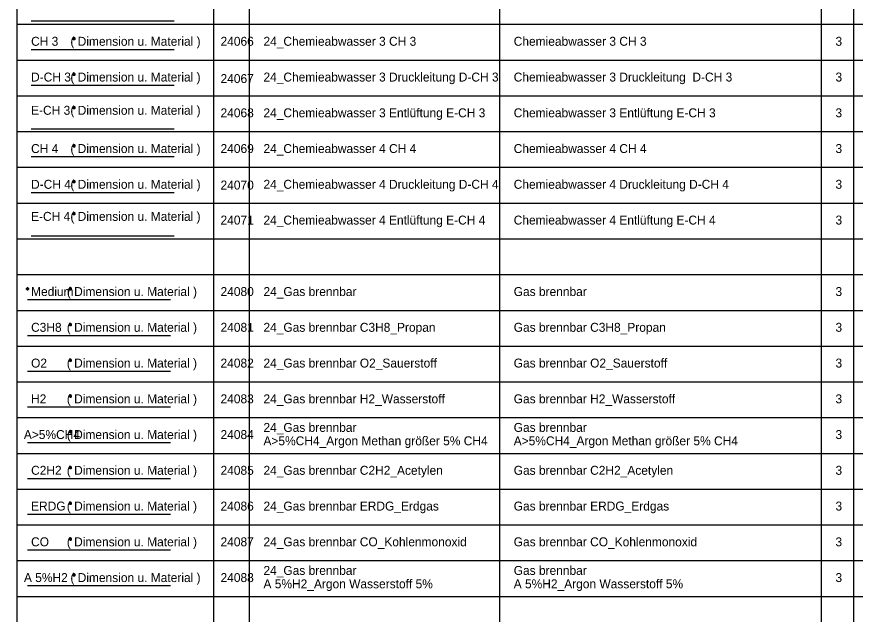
# Model space of a CAD drawing. Extents: x -29 to 48, y -113 to 16.
# Drawn here: x 0 to 23.45, y -47.5 to -30.79 of the extents above; entities that cross this region are included whole.
import ezdxf

# ---------------------------------------------------------------- set-up
doc = ezdxf.new("R2010")
doc.units = 0
for name, color, linetype in [('24_Chemieabwasser 2 Entlüftung E-CH2', 7, 'Continuous'), ('24_Chemieabwasser 3 CH 3', 7, 'Continuous'), ('24_Chemieabwasser 3 Druckleitung D-CH 3', 7, 'Continuous'), ('24_Chemieabwasser 3 Entlüftung E-CH 3', 7, 'Continuous'), ('24_Chemieabwasser 4 CH 4', 7, 'Continuous'), ('24_Chemieabwasser 4 Druckleitung CH 4', 7, 'Continuous'), ('24_Chemieabwasser 4 Entlüftung E-CH 4', 7, 'Continuous'), ('24_Gas brennbar', 7, 'Continuous'), ('24_Gas brennbar A 5%H2_Argon Wasserstoff 5%', 7, 'Continuous'), ('24_Gas brennbar A-5%CH4_Argon Methan größer 5% CH4', 7, 'Continuous'), ('24_Gas brennbar C2H2_Acetylen', 7, 'Continuous'), ('24_Gas brennbar C3H8_Propan', 7, 'Continuous'), ('24_Gas brennbar CO_Kohlenmonoxid', 7, 'Continuous'), ('24_Gas brennbar ERDG_Erdgas', 7, 'Continuous'), ('24_Gas brennbar H2_Wasserstoff', 7, 'Continuous'), ('24_Gas brennbar O2_Sauerstoff', 7, 'Continuous'), ('Default', 7, 'Continuous')]:
    doc.layers.add(name, color=color, linetype=linetype)

msp = doc.modelspace()

# ---------------------------------------------------------------- linework, layer by layer
at = {"layer": '24_Chemieabwasser 2 Entlüftung E-CH2'}
msp.add_line((0.4, -30.902), (4.4, -30.902), dxfattribs=at)
at = {"layer": '24_Chemieabwasser 3 CH 3'}
for p, q in [((1.556, -31.4), (1.644, -31.4)), ((1.569, -31.369), (1.631, -31.431)), ((1.631, -31.369), (1.569, -31.431)), ((1.6, -31.356), (1.6, -31.444)), ((0.4, -31.7), (4.4, -31.7)), ((1.6, -32.356), (1.6, -32.444)), ((1.556, -32.4), (1.644, -32.4)), ((1.569, -32.369), (1.631, -32.431)), ((1.631, -32.369), (1.569, -32.431))]:
    msp.add_line(p, q, dxfattribs=at)
at = {"layer": '24_Chemieabwasser 3 Druckleitung D-CH 3'}
msp.add_line((0.4, -32.7), (4.4, -32.7), dxfattribs=at)
at = {"layer": '24_Chemieabwasser 3 Entlüftung E-CH 3'}
for p, q in [((1.569, -33.299), (1.631, -33.361)), ((1.631, -33.299), (1.569, -33.361)), ((1.6, -33.286), (1.6, -33.374)), ((1.556, -33.33), (1.644, -33.33)), ((0.4, -33.922), (4.4, -33.922))]:
    msp.add_line(p, q, dxfattribs=at)
at = {"layer": '24_Chemieabwasser 4 CH 4'}
for p, q in [((1.556, -34.4), (1.644, -34.4)), ((1.569, -34.369), (1.631, -34.431)), ((1.631, -34.369), (1.569, -34.431)), ((1.6, -34.356), (1.6, -34.444)), ((0.4, -34.7), (4.4, -34.7)), ((1.556, -35.4), (1.644, -35.4))]:
    msp.add_line(p, q, dxfattribs=at)
at = {"layer": '24_Chemieabwasser 4 Druckleitung CH 4'}
for p, q in [((1.569, -35.369), (1.631, -35.431)), ((1.631, -35.369), (1.569, -35.431)), ((1.6, -35.356), (1.6, -35.444)), ((0.4, -35.7), (4.4, -35.7))]:
    msp.add_line(p, q, dxfattribs=at)
at = {"layer": '24_Chemieabwasser 4 Entlüftung E-CH 4'}
for p, q in [((1.556, -36.297), (1.644, -36.297)), ((1.569, -36.265), (1.631, -36.328)), ((1.631, -36.265), (1.569, -36.328)), ((1.6, -36.252), (1.6, -36.341)), ((0.4, -36.916), (4.4, -36.916))]:
    msp.add_line(p, q, dxfattribs=at)
at = {"layer": '24_Gas brennbar'}
for p, q in [((0.256, -38.4), (0.344, -38.4)), ((0.269, -38.369), (0.331, -38.431)), ((0.331, -38.369), (0.269, -38.431)), ((0.3, -38.356), (0.3, -38.444)), ((1.456, -38.4), (1.544, -38.4)), ((1.469, -38.369), (1.531, -38.431)), ((1.531, -38.369), (1.469, -38.431)), ((1.5, -38.356), (1.5, -38.444)), ((0.3, -38.7), (4.3, -38.7))]:
    msp.add_line(p, q, dxfattribs=at)
at = {"layer": '24_Gas brennbar A 5%H2_Argon Wasserstoff 5%'}
for p, q in [((1.556, -46.4), (1.644, -46.4)), ((1.569, -46.369), (1.631, -46.431)), ((1.631, -46.369), (1.569, -46.431)), ((1.6, -46.356), (1.6, -46.444)), ((0.3, -46.7), (4.3, -46.7))]:
    msp.add_line(p, q, dxfattribs=at)
at = {"layer": '24_Gas brennbar A-5%CH4_Argon Methan größer 5% CH4'}
for p, q in [((1.458, -42.4), (1.546, -42.4)), ((1.471, -42.369), (1.533, -42.431)), ((1.533, -42.369), (1.471, -42.431)), ((1.502, -42.356), (1.502, -42.444)), ((0.3, -42.7), (4.3, -42.7))]:
    msp.add_line(p, q, dxfattribs=at)
at = {"layer": '24_Gas brennbar C2H2_Acetylen'}
for p, q in [((1.469, -43.369), (1.531, -43.431)), ((1.531, -43.369), (1.469, -43.431)), ((1.5, -43.356), (1.5, -43.444)), ((1.456, -43.4), (1.544, -43.4)), ((0.3, -43.7), (4.3, -43.7))]:
    msp.add_line(p, q, dxfattribs=at)
at = {"layer": '24_Gas brennbar C3H8_Propan'}
for p, q in [((1.456, -39.4), (1.544, -39.4)), ((1.469, -39.369), (1.531, -39.431)), ((1.531, -39.369), (1.469, -39.431)), ((1.5, -39.356), (1.5, -39.444)), ((0.3, -39.7), (4.3, -39.7))]:
    msp.add_line(p, q, dxfattribs=at)
at = {"layer": '24_Gas brennbar CO_Kohlenmonoxid'}
for p, q in [((1.456, -45.4), (1.544, -45.4)), ((1.469, -45.369), (1.531, -45.431)), ((1.531, -45.369), (1.469, -45.431)), ((1.5, -45.356), (1.5, -45.444)), ((0.3, -45.7), (4.3, -45.7))]:
    msp.add_line(p, q, dxfattribs=at)
at = {"layer": '24_Gas brennbar ERDG_Erdgas'}
for p, q in [((1.456, -44.4), (1.544, -44.4)), ((1.469, -44.369), (1.531, -44.431)), ((1.531, -44.369), (1.469, -44.431)), ((1.5, -44.356), (1.5, -44.444)), ((0.3, -44.7), (4.3, -44.7))]:
    msp.add_line(p, q, dxfattribs=at)
at = {"layer": '24_Gas brennbar H2_Wasserstoff'}
for p, q in [((1.456, -41.4), (1.544, -41.4)), ((1.469, -41.369), (1.531, -41.431)), ((1.531, -41.369), (1.469, -41.431)), ((1.5, -41.356), (1.5, -41.444)), ((0.3, -41.7), (4.3, -41.7))]:
    msp.add_line(p, q, dxfattribs=at)
at = {"layer": '24_Gas brennbar O2_Sauerstoff'}
for p, q in [((1.456, -40.4), (1.544, -40.4)), ((1.469, -40.369), (1.531, -40.431)), ((1.531, -40.369), (1.469, -40.431)), ((1.5, -40.356), (1.5, -40.444)), ((0.3, -40.7), (4.3, -40.7))]:
    msp.add_line(p, q, dxfattribs=at)
at = {"layer": 'Default'}
for p, q in [((0, 0), (0, -107)), ((5.5, 0), (5.5, -107)), ((6.5, 0), (6.5, -107)), ((13.5, 0), (13.5, -107)), ((22.5, 0), (22.5, -107)), ((23.4, -0.7), (23.4, -89)), ((0, -31), (32, -31)), ((0, -32), (32, -32)), ((0, -33), (32, -33)), ((0, -34), (32, -34)), ((0, -35), (32, -35)), ((0, -36), (32, -36)), ((0, -37), (32, -37)), ((0, -38), (32, -38)), ((0, -39), (32, -39)), ((0, -40), (32, -40)), ((0, -41), (32, -41)), ((0, -42), (32, -42)), ((0, -43), (32, -43)), ((0, -44), (32, -44)), ((0, -45), (32, -45)), ((0, -46), (32, -46)), ((0, -47), (32, -47))]:
    msp.add_line(p, q, dxfattribs=at)

# ---------------------------------------------------------------- texts
at = {"layer": '24_Chemieabwasser 3 CH 3'}
for s, p in [('CH 3', (0.4, -31.6)), ('( Dimension u. Material )', (1.5, -31.6))]:
    msp.add_text(s, height=0.25, dxfattribs=at).set_placement(p)
at = {"layer": '24_Chemieabwasser 3 Druckleitung D-CH 3'}
for s, p in [('D-CH 3', (0.4, -32.6)), ('( Dimension u. Material )', (1.5, -32.6))]:
    msp.add_text(s, height=0.25, dxfattribs=at).set_placement(p)
at = {"layer": '24_Chemieabwasser 3 Entlüftung E-CH 3'}
for s, p in [('E-CH 3', (0.4, -33.53)), ('( Dimension u. Material )', (1.5, -33.53))]:
    msp.add_text(s, height=0.25, dxfattribs=at).set_placement(p)
at = {"layer": '24_Chemieabwasser 4 CH 4'}
for s, p in [('CH 4', (0.4, -34.6)), ('( Dimension u. Material )', (1.5, -34.6))]:
    msp.add_text(s, height=0.25, dxfattribs=at).set_placement(p)
at = {"layer": '24_Chemieabwasser 4 Druckleitung CH 4'}
for s, p in [('D-CH 4', (0.4, -35.6)), ('( Dimension u. Material )', (1.5, -35.6))]:
    msp.add_text(s, height=0.25, dxfattribs=at).set_placement(p)
at = {"layer": '24_Chemieabwasser 4 Entlüftung E-CH 4'}
for s, p in [('E-CH 4', (0.4, -36.497)), ('( Dimension u. Material )', (1.5, -36.497))]:
    msp.add_text(s, height=0.25, dxfattribs=at).set_placement(p)
at = {"layer": '24_Gas brennbar'}
for s, p in [('Medium', (0.4, -38.6)), ('( Dimension u. Material )', (1.4, -38.6))]:
    msp.add_text(s, height=0.25, dxfattribs=at).set_placement(p)
at = {"layer": '24_Gas brennbar A 5%H2_Argon Wasserstoff 5%'}
for s, p in [('A 5%H2', (0.2, -46.6)), ('( Dimension u. Material )', (1.5, -46.6))]:
    msp.add_text(s, height=0.25, dxfattribs=at).set_placement(p)
at = {"layer": '24_Gas brennbar A-5%CH4_Argon Methan größer 5% CH4'}
for s, p in [('A>5%CH4', (0.198, -42.6)), ('( Dimension u. Material )', (1.4, -42.6))]:
    msp.add_text(s, height=0.25, dxfattribs=at).set_placement(p)
at = {"layer": '24_Gas brennbar C2H2_Acetylen'}
for s, p in [('C2H2', (0.4, -43.6)), ('( Dimension u. Material )', (1.4, -43.6))]:
    msp.add_text(s, height=0.25, dxfattribs=at).set_placement(p)
at = {"layer": '24_Gas brennbar C3H8_Propan'}
for s, p in [('C3H8', (0.4, -39.6)), ('( Dimension u. Material )', (1.4, -39.6))]:
    msp.add_text(s, height=0.25, dxfattribs=at).set_placement(p)
at = {"layer": '24_Gas brennbar CO_Kohlenmonoxid'}
for s, p in [('CO', (0.4, -45.6)), ('( Dimension u. Material )', (1.4, -45.6))]:
    msp.add_text(s, height=0.25, dxfattribs=at).set_placement(p)
at = {"layer": '24_Gas brennbar ERDG_Erdgas'}
for s, p in [('ERDG', (0.4, -44.6)), ('( Dimension u. Material )', (1.4, -44.6))]:
    msp.add_text(s, height=0.25, dxfattribs=at).set_placement(p)
at = {"layer": '24_Gas brennbar H2_Wasserstoff'}
for s, p in [('H2', (0.4, -41.6)), ('( Dimension u. Material )', (1.4, -41.6))]:
    msp.add_text(s, height=0.25, dxfattribs=at).set_placement(p)
at = {"layer": '24_Gas brennbar O2_Sauerstoff'}
for s, p in [('( Dimension u. Material )', (1.4, -40.6)), ('O2', (0.4, -40.6))]:
    msp.add_text(s, height=0.25, dxfattribs=at).set_placement(p)
at = {"layer": 'Default'}
for s, p in [('24066', (5.7, -31.6)), ('24_Chemieabwasser 3 CH 3', (6.9, -31.6)), ('Chemieabwasser 3 CH 3', (13.9, -31.6)), ('3', (22.9, -31.6)), ('24_Chemieabwasser 3 Druckleitung D-CH 3', (6.9, -32.6)), ('Chemieabwasser 3 Druckleitung  D-CH 3', (13.9, -32.6)), ('3', (22.9, -32.6)), ('24067', (5.7, -32.643)), ('24068', (5.7, -33.6)), ('24_Chemieabwasser 3 Entlüftung E-CH 3', (6.9, -33.6)), ('Chemieabwasser 3 Entlüftung E-CH 3', (13.9, -33.6)), ('3', (22.9, -33.6)), ('24069', (5.7, -34.6)), ('24_Chemieabwasser 4 CH 4', (6.9, -34.6)), ('Chemieabwasser 4 CH 4', (13.9, -34.6)), ('3', (22.9, -34.6)), ('24070', (5.7, -35.621)), ('24_Chemieabwasser 4 Druckleitung D-CH 4', (6.9, -35.6)), ('Chemieabwasser 4 Druckleitung D-CH 4', (13.9, -35.6)), ('3', (22.9, -35.6)), ('24071', (5.7, -36.6)), ('24_Chemieabwasser 4 Entlüftung E-CH 4', (6.9, -36.6)), ('Chemieabwasser 4 Entlüftung E-CH 4', (13.9, -36.6)), ('3', (22.9, -36.6)), ('24080', (5.7, -38.6)), ('24_Gas brennbar', (6.9, -38.6)), ('Gas brennbar', (13.9, -38.6)), ('3', (22.9, -38.6)), ('24081', (5.7, -39.6)), ('24_Gas brennbar C3H8_Propan', (6.9, -39.6)), ('Gas brennbar C3H8_Propan', (13.9, -39.6)), ('3', (22.9, -39.6)), ('24_Gas brennbar O2_Sauerstoff', (6.9, -40.6)), ('Gas brennbar O2_Sauerstoff', (13.9, -40.6)), ('24082', (5.7, -40.6)), ('3', (22.9, -40.6)), ('24083', (5.7, -41.6)), ('24_Gas brennbar H2_Wasserstoff', (6.9, -41.6)), ('Gas brennbar H2_Wasserstoff', (13.9, -41.6)), ('3', (22.9, -41.6)), ('24_Gas brennbar', (6.9, -42.4)), ('Gas brennbar', (13.9, -42.4)), ('24084', (5.7, -42.6)), ('3', (22.9, -42.6)), ('A>5%CH4_Argon Methan größer 5% CH4', (6.9, -42.775)), ('A>5%CH4_Argon Methan größer 5% CH4', (13.9, -42.775)), ('24085', (5.7, -43.6)), ('24_Gas brennbar C2H2_Acetylen', (6.9, -43.6)), ('Gas brennbar C2H2_Acetylen', (13.9, -43.6)), ('3', (22.9, -43.6)), ('24086', (5.7, -44.6)), ('24_Gas brennbar ERDG_Erdgas', (6.9, -44.6)), ('Gas brennbar ERDG_Erdgas', (13.9, -44.6)), ('3', (22.9, -44.6)), ('24087', (5.7, -45.6)), ('24_Gas brennbar CO_Kohlenmonoxid', (6.9, -45.6)), ('Gas brennbar CO_Kohlenmonoxid', (13.9, -45.6)), ('3', (22.9, -45.6)), ('24_Gas brennbar ', (6.9, -46.4)), ('Gas brennbar ', (13.9, -46.4)), ('24088', (5.7, -46.6)), ('3', (22.9, -46.6)), ('A 5%H2_Argon Wasserstoff 5%', (6.9, -46.775)), ('A 5%H2_Argon Wasserstoff 5%', (13.9, -46.775))]:
    msp.add_text(s, height=0.25, dxfattribs=at).set_placement(p)

doc.saveas('drawing.dxf')
